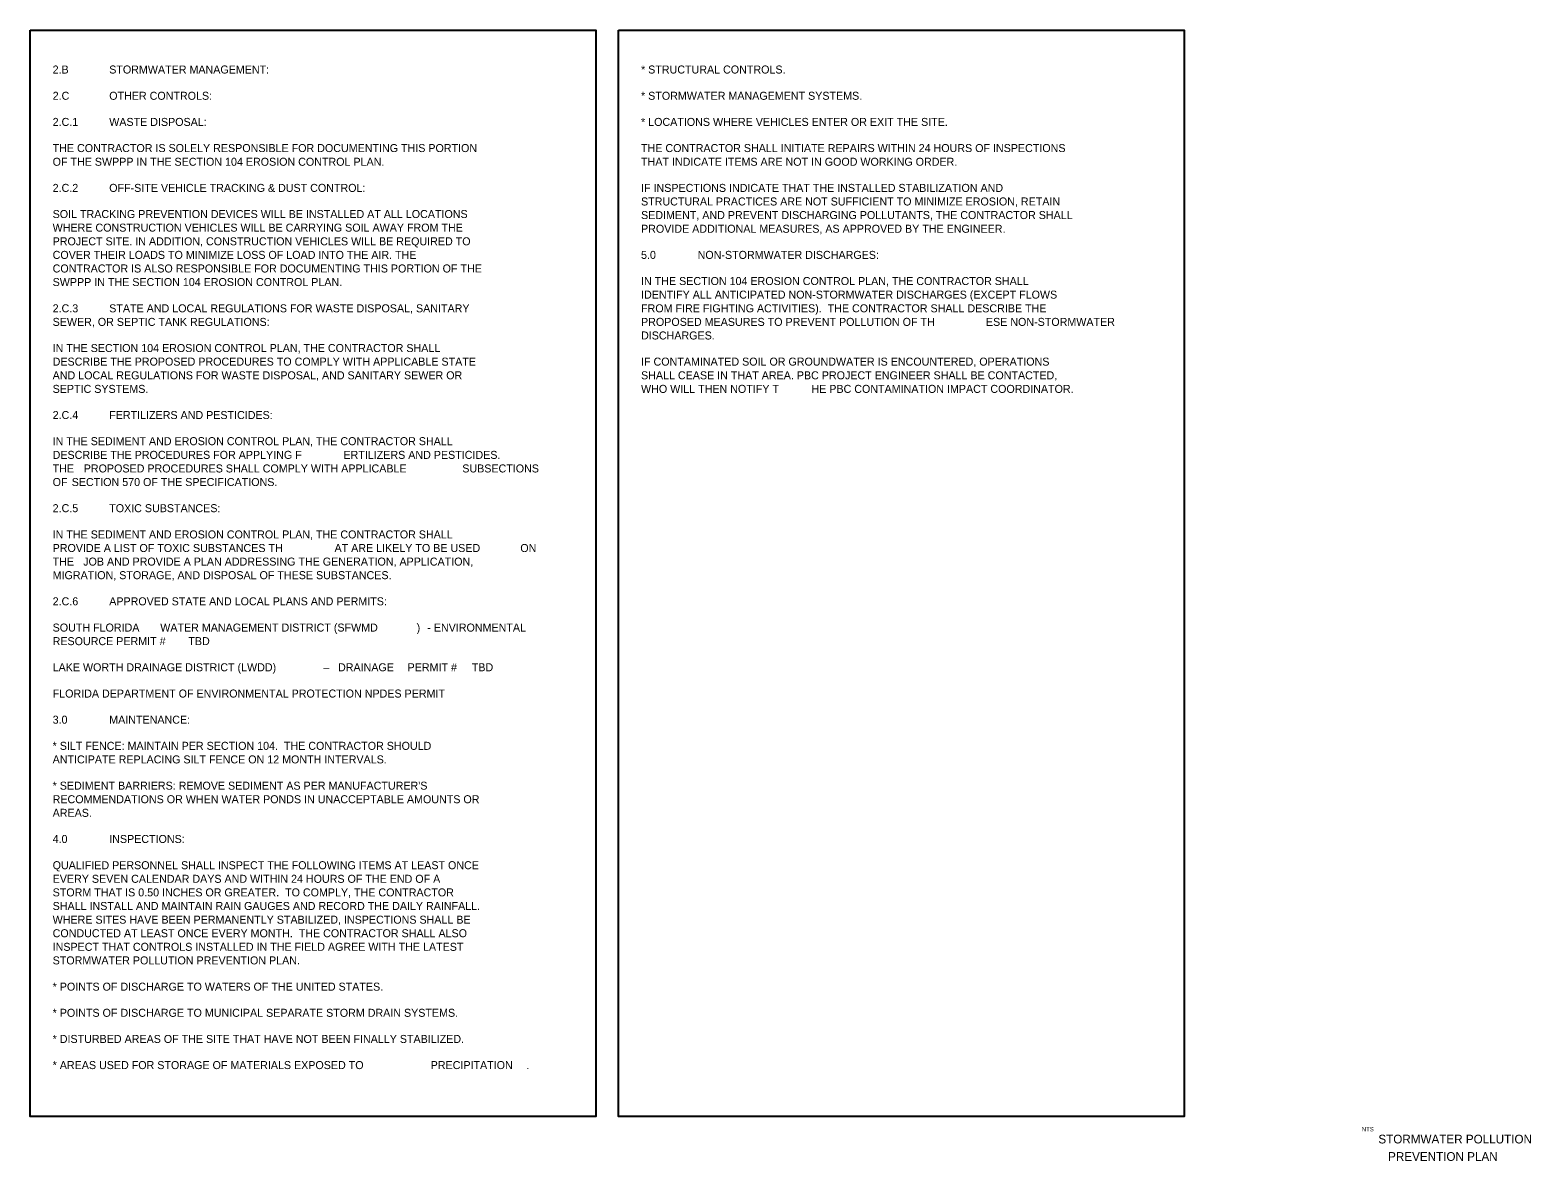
# Model space of a CAD drawing. Extents: x 0 to 15.4, y -12.3 to 9.6.
# Drawn here: x 0 to 13.26, y -12.29 to -2.3 of the extents above; entities that cross this region are included whole.
import ezdxf

# ---------------------------------------------------------------- set-up
doc = ezdxf.new("R2010")
doc.units = 0
for name, color, linetype in [('ConstLines', 7, 'Continuous'), ('Default', 7, 'Continuous'), ('TextNotes', 7, 'Continuous')]:
    doc.layers.add(name, color=color, linetype=linetype)

msp = doc.modelspace()

# ---------------------------------------------------------------- linework, layer by layer
at = {"layer": 'ConstLines'}
for points in [[(0, -2.302), (5, -2.302), (5, -11.902), (0, -11.902)], [(5.2, -2.302), (10.2, -2.302), (10.2, -11.902), (5.2, -11.902)]]:
    msp.add_lwpolyline(points, close=True, dxfattribs=at)

# ---------------------------------------------------------------- texts
at = {"layer": 'Default'}
for s, height, p in [('NTS', 0.0385, (11.769, -12.033)), ('        STORMWATER POLLUTION        ', 0.07709, (11.687, -12.14)), ('           PREVENTION PLAN', 0.07709, (11.687, -12.294))]:
    msp.add_text(s, height=height, dxfattribs=at).set_placement(p)
at = {"layer": 'TextNotes'}
for s, height, p in [('2.B', 0.0707, (0.2, -2.686)), ('STORMWATER MANAGEMENT:', 0.07071, (0.7, -2.686)), ('* STRUCTURAL CONTROLS.', 0.07071, (5.4, -2.686)), ('2.C', 0.0707, (0.2, -2.918)), ('OTHER CONTROLS:', 0.07071, (0.7, -2.918)), ('* STORMWATER MANAGEMENT SYSTEMS.', 0.07071, (5.4, -2.918)), ('2.C.1', 0.0707, (0.2, -3.149)), ('WASTE DISPOSAL:', 0.07071, (0.7, -3.149)), ('* LOCATIONS WHERE VEHICLES ENTER OR EXIT THE SITE.', 0.07071, (5.4, -3.149)), ('THE CONTRACTOR IS SOLELY RESPONSIBLE FOR DOCUMENTING THIS PORTION ', 0.07071, (0.2, -3.38)), ('THE CONTRACTOR SHALL INITIATE REPAIRS WITHIN 24 HOURS OF INSPECTIONS ', 0.07071, (5.4, -3.38)), ('OF THE SWPPP IN THE SECTION 104 EROSION CONTROL PLAN.', 0.07071, (0.2, -3.501)), ('THAT INDICATE ITEMS ARE NOT IN GOOD WORKING ORDER.', 0.07071, (5.4, -3.501)), ('2.C.2', 0.0707, (0.2, -3.732)), ('OFF-SITE VEHICLE TRACKING & DUST CONTROL:', 0.07071, (0.7, -3.732)), ('IF INSPECTIONS INDICATE THAT THE INSTALLED STABILIZATION AND ', 0.07071, (5.4, -3.732)), ('STRUCTURAL PRACTICES ARE NOT SUFFICIENT TO MINIMIZE EROSION, RETAIN ', 0.07071, (5.4, -3.852)), ('SOIL TRACKING PREVENTION DEVICES WILL BE INSTALLED AT ALL LOCATIONS ', 0.07071, (0.2, -3.963)), ('SEDIMENT, AND PREVENT DISCHARGING POLLUTANTS, THE CONTRACTOR SHALL ', 0.07071, (5.4, -3.972)), ('WHERE CONSTRUCTION VEHICLES WILL BE CARRYING SOIL AWAY FROM THE ', 0.07071, (0.2, -4.083)), ('PROVIDE ADDITIONAL MEASURES, AS APPROVED BY THE ENGINEER.', 0.07071, (5.4, -4.093)), ('PROJECT SITE. IN ADDITION, CONSTRUCTION VEHICLES WILL BE REQUIRED TO ', 0.07071, (0.2, -4.204)), ('COVER THEIR LOADS TO MINIMIZE LOSS OF LOAD INTO THE AIR. THE ', 0.07071, (0.2, -4.324)), ('CONTRACTOR IS ALSO RESPONSIBLE FOR DOCUMENTING THIS PORTION OF THE ', 0.07071, (0.2, -4.444)), ('5.0', 0.0707, (5.4, -4.324)), ('NON-STORMWATER DISCHARGES:', 0.07071, (5.9, -4.324)), ('SWPPP IN THE SECTION 104 EROSION CONTROL PLAN.', 0.07071, (0.2, -4.564)), ('IN THE SECTION 104 EROSION CONTROL PLAN, THE CONTRACTOR SHALL ', 0.07071, (5.4, -4.555)), ('IDENTIFY ALL ANTICIPATED NON-STORMWATER DISCHARGES (EXCEPT FLOWS ', 0.07071, (5.4, -4.675)), ('2.C.3', 0.0707, (0.2, -4.796)), ('STATE AND LOCAL REGULATIONS FOR WASTE DISPOSAL, SANITARY ', 0.07071, (0.7, -4.796)), ('FROM FIRE FIGHTING ACTIVITIES).  THE CONTRACTOR SHALL DESCRIBE THE ', 0.07071, (5.4, -4.796)), ('SEWER, OR SEPTIC TANK REGULATIONS:', 0.07071, (0.2, -4.916)), ('PROPOSED MEASURES TO PREVENT POLLUTION OF TH', 0.07071, (5.4, -4.916)), ('ESE NON-STORMWATER ', 0.07071, (8.448, -4.916)), ('DISCHARGES. ', 0.07071, (5.4, -5.036)), ('IN THE SECTION 104 EROSION CONTROL PLAN, THE CONTRACTOR SHALL ', 0.07071, (0.2, -5.147)), ('DESCRIBE THE PROPOSED PROCEDURES TO COMPLY WITH APPLICABLE STATE ', 0.07071, (0.2, -5.267)), ('IF CONTAMINATED SOIL OR GROUNDWATER IS ENCOUNTERED, OPERATIONS ', 0.07071, (5.4, -5.267)), ('AND LOCAL REGULATIONS FOR WASTE DISPOSAL, AND SANITARY SEWER OR ', 0.07071, (0.2, -5.388)), ('SEPTIC SYSTEMS.', 0.07071, (0.2, -5.508)), ('WHO WILL THEN NOTIFY T', 0.07071, (5.4, -5.508)), ('SHALL CEASE IN THAT AREA. PBC PROJECT ENGINEER SHALL BE CONTACTED, ', 0.07071, (5.4, -5.388)), ('HE PBC CONTAMINATION IMPACT COORDINATOR.', 0.07071, (6.906, -5.508)), ('2.C.4', 0.0707, (0.2, -5.739)), ('FERTILIZERS AND PESTICIDES:', 0.07071, (0.7, -5.739)), ('IN THE SEDIMENT AND EROSION CONTROL PLAN, THE CONTRACTOR SHALL ', 0.07071, (0.2, -5.97)), ('DESCRIBE THE PROCEDURES FOR APPLYING F', 0.07071, (0.2, -6.091)), ('ERTILIZERS AND PESTICIDES.  ', 0.07071, (2.77, -6.091)), ('THE ', 0.0707, (0.2, -6.211)), ('PROPOSED PROCEDURES SHALL COMPLY WITH APPLICABLE ', 0.07071, (0.475, -6.211)), ('SUBSECTIONS ', 0.07071, (3.82, -6.211)), ('OF', 0.0707, (0.2, -6.331)), (' SECTION 570 OF THE SPECIFICATIONS.', 0.07071, (0.342, -6.331)), ('2.C.5', 0.0707, (0.2, -6.562)), ('TOXIC SUBSTANCES:', 0.07071, (0.7, -6.562)), ('IN THE SEDIMENT AND EROSION CONTROL PLAN, THE CONTRACTOR SHALL ', 0.07071, (0.2, -6.794)), ('PROVIDE A LIST OF TOXIC SUBSTANCES TH', 0.07071, (0.2, -6.914)), ('AT ARE LIKELY TO BE USED ', 0.07071, (2.691, -6.914)), ('ON ', 0.0707, (4.333, -6.914)), ('THE', 0.0707, (0.2, -7.034)), ('JOB AND PROVIDE A PLAN ADDRESSING THE GENERATION, APPLICATION, ', 0.07071, (0.47, -7.034)), ('MIGRATION, STORAGE, AND DISPOSAL OF THESE SUBSTANCES.', 0.07071, (0.2, -7.154)), ('2.C.6', 0.0707, (0.2, -7.385)), ('APPROVED STATE AND LOCAL PLANS AND PERMITS:', 0.07071, (0.7, -7.385)), ('SOUTH FLORIDA ', 0.07071, (0.2, -7.617)), ('WATER MANAGEMENT DISTRICT (SFWMD', 0.07071, (1.151, -7.617)), (')', 0.0707, (3.417, -7.617)), ('- ENVIRONMENTAL ', 0.07071, (3.511, -7.617)), ('RESOURCE PERMIT #', 0.07071, (0.2, -7.737)), (' TBD', 0.0707, (1.373, -7.737)), ('LAKE WORTH DRAINAGE DISTRICT (LWDD)', 0.07071, (0.2, -7.968)), (' –', 0.0707, (2.567, -7.968)), ('DRAINAGE ', 0.0707, (2.722, -7.968)), ('PERMIT #', 0.0707, (3.337, -7.968)), (' TBD', 0.0707, (3.878, -7.968)), ('FLORIDA DEPARTMENT OF ENVIRONMENTAL PROTECTION NPDES PERMIT', 0.07071, (0.2, -8.2)), ('3.0', 0.0707, (0.2, -8.431)), ('MAINTENANCE:', 0.07071, (0.7, -8.431)), ('* SILT FENCE: MAINTAIN PER SECTION 104.  THE CONTRACTOR SHOULD ', 0.07071, (0.2, -8.662)), ('ANTICIPATE REPLACING SILT FENCE ON 12 MONTH INTERVALS. ', 0.07071, (0.2, -8.782)), ("* SEDIMENT BARRIERS: REMOVE SEDIMENT AS PER MANUFACTURER'S ", 0.07071, (0.2, -9.014)), ('RECOMMENDATIONS OR WHEN WATER PONDS IN UNACCEPTABLE AMOUNTS OR ', 0.07071, (0.2, -9.134)), ('AREAS.', 0.0707, (0.2, -9.254)), ('4.0', 0.0707, (0.2, -9.485)), ('INSPECTIONS:', 0.07071, (0.7, -9.485)), ('QUALIFIED PERSONNEL SHALL INSPECT THE FOLLOWING ITEMS AT LEAST ONCE ', 0.07071, (0.2, -9.717)), ('EVERY SEVEN CALENDAR DAYS AND WITHIN 24 HOURS OF THE END OF A ', 0.07071, (0.2, -9.837)), ('STORM THAT IS 0.50 INCHES OR GREATER.  TO COMPLY, THE CONTRACTOR', 0.07071, (0.2, -9.957)), ('SHALL INSTALL AND MAINTAIN RAIN GAUGES AND RECORD THE DAILY RAINFALL.', 0.07071, (0.2, -10.077)), ('WHERE SITES HAVE BEEN PERMANENTLY STABILIZED, INSPECTIONS SHALL BE ', 0.07071, (0.2, -10.198)), ('CONDUCTED AT LEAST ONCE EVERY MONTH.  THE CONTRACTOR SHALL ALSO ', 0.07071, (0.2, -10.318)), ('INSPECT THAT CONTROLS INSTALLED IN THE FIELD AGREE WITH THE LATEST ', 0.07071, (0.2, -10.438)), ('STORMWATER POLLUTION PREVENTION PLAN.', 0.07071, (0.2, -10.558)), ('* POINTS OF DISCHARGE TO WATERS OF THE UNITED STATES.', 0.07071, (0.2, -10.79)), ('* POINTS OF DISCHARGE TO MUNICIPAL SEPARATE STORM DRAIN SYSTEMS.', 0.07071, (0.2, -11.021)), ('* DISTURBED AREAS OF THE SITE THAT HAVE NOT BEEN FINALLY STABILIZED.', 0.07071, (0.2, -11.252)), ('* AREAS USED FOR STORAGE OF MATERIALS EXPOSED TO', 0.07071, (0.2, -11.483)), ('PRECIPITATION', 0.07071, (3.541, -11.483)), ('.', 0.0707, (4.385, -11.483))]:
    msp.add_text(s, height=height, dxfattribs=at).set_placement(p)

doc.saveas('drawing.dxf')
